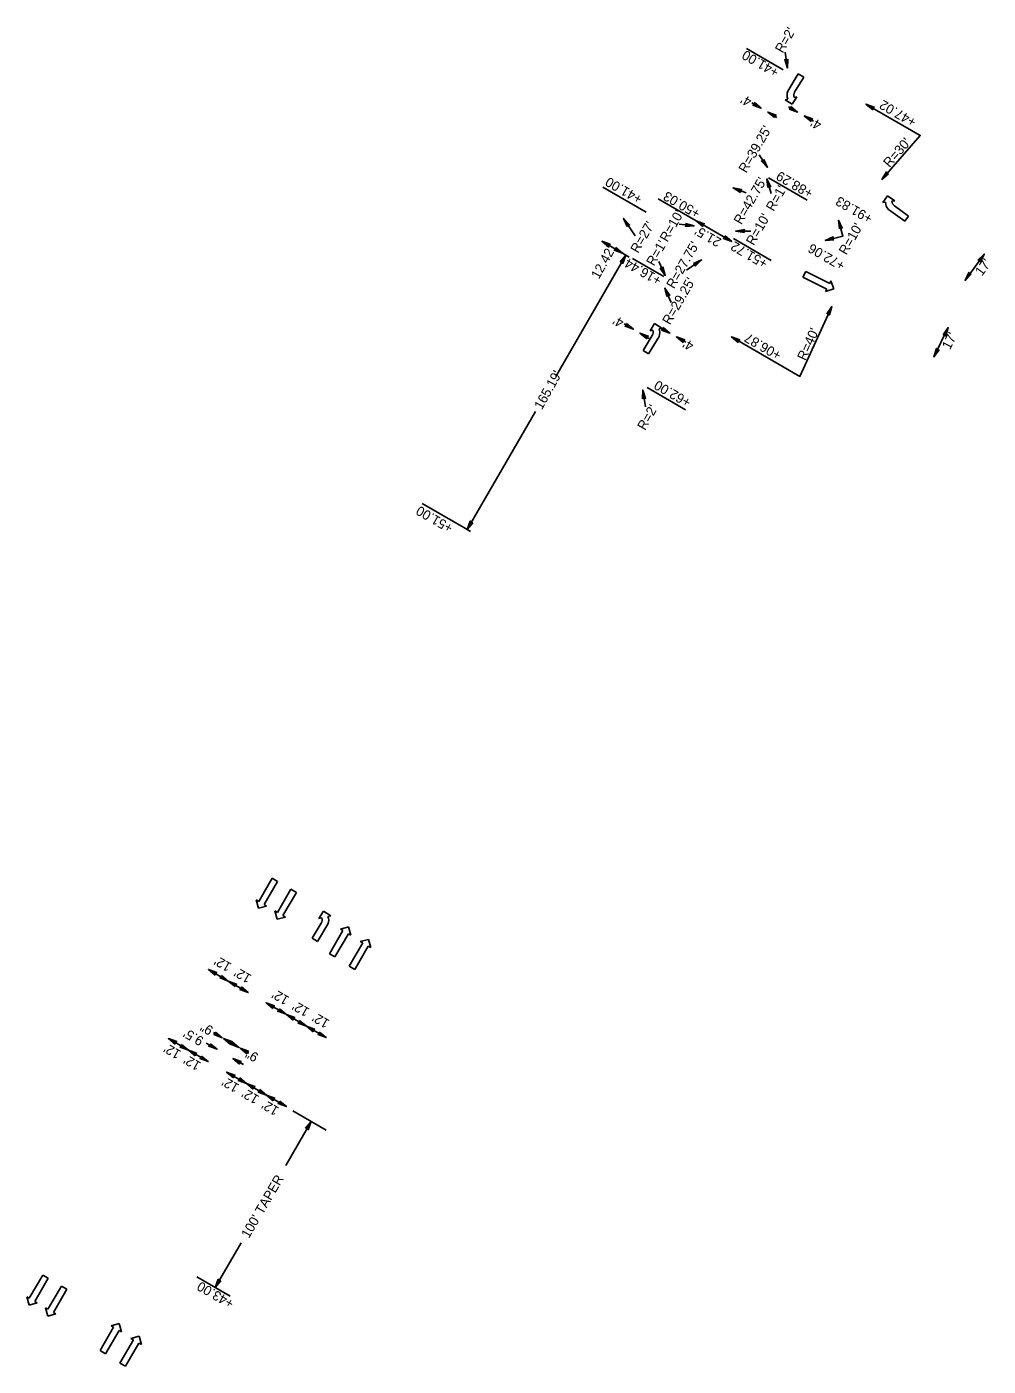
# Model space of a CAD drawing. Extents: x 2320991 to 2332664, y 598057 to 612602.
# Drawn here: x 2329700 to 2330201, y 609336 to 610034 of the extents above; entities that cross this region are included whole.
import ezdxf

# ---------------------------------------------------------------- set-up
doc = ezdxf.new("R2010")
doc.units = 0
for name, color, linetype in [('Prop Dimension', 7, 'Continuous'), ('Prop Dimension Text', 7, 'Continuous'), ('Prop Lane Arrow CELL', 7, 'Continuous'), ('Prop Terminator CELL', 7, 'Continuous')]:
    doc.layers.add(name, color=color, linetype=linetype)

msp = doc.modelspace()

# ---------------------------------------------------------------- linework, layer by layer
at = {"layer": 'Prop Dimension'}
for p, q in [((2330094.28, 610011.7), (2330075.14, 610022.76)), ((2330096.45, 610012.65), (2330095.27, 610020.99)), ((2330077.91, 609994.47), (2330082.72, 609991.69)), ((2330086.18, 609989.69), (2330090.98, 609986.92)), ((2330096.95, 609992.44), (2330101.76, 609989.66)), ((2330105.22, 609987.66), (2330110.02, 609984.88)), ((2330085.97, 609960.8), (2330081.7, 609967.34)), ((2330085.72, 609954.84), (2330087.89, 609947.22)), ((2330086.54, 609955.33), (2330106.75, 609943.66)), ((2330022.81, 609937.49), (2330000.24, 609950.54)), ((2330074.83, 609947.48), (2330068.06, 609950.16)), ((2330048.78, 609932.97), (2330028.97, 609944.42)), ((2330010.96, 609934.18), (2330016.97, 609925.17)), ((2330048.78, 609932.97), (2330067.4, 609922.21)), ((2330047.72, 609930.33), (2330039.95, 609931.17)), ((2330069.52, 609927.59), (2330077.28, 609927.62)), ((2329999.67, 609922.28), (2330010.42, 609916.06)), ((2330068.24, 609923.67), (2330087.95, 609912.28)), ((2329975.62, 609851.84), (2330012.15, 609915.06)), ((2330010.42, 609916.06), (2330013.89, 609914.06)), ((2330031.97, 609903.89), (2330015.68, 609913.31)), ((2330032.69, 609904.48), (2330029.39, 609911.69)), ((2330043.81, 609907.25), (2330051.64, 609912.55)), ((2330189.01, 609901.91), (2330199.02, 609915.65)), ((2330035.8, 609890.29), (2330032.56, 609897.92)), ((2330011.28, 609879.2), (2330016.09, 609876.42)), ((2330030.32, 609877.17), (2330035.13, 609874.39)), ((2330172.77, 609862.03), (2330180.3, 609877.27)), ((2330019.56, 609874.42), (2330024.35, 609871.65)), ((2330038.59, 609872.39), (2330043.39, 609869.62)), ((2330020.98, 609844.73), (2330022.36, 609835.89)), ((2330023.35, 609846), (2330043.34, 609834.44)), ((2329929.49, 609772.03), (2329965.08, 609833.6)), ((2329927.76, 609773.04), (2329906.01, 609785.61)), ((2329927.76, 609773.04), (2329931.23, 609771.03)), ((2329804.93, 609536.53), (2329794.55, 609542.55)), ((2329815.32, 609530.52), (2329804.93, 609536.53)), ((2329835.03, 609519.16), (2329824.65, 609525.18)), ((2329845.63, 609513.03), (2329835.25, 609519.04)), ((2329797.19, 609509.62), (2329801.72, 609506.99)), ((2329802.36, 609506.61), (2329806.89, 609503.99)), ((2329856.02, 609507.02), (2329845.63, 609513.03)), ((2329784.11, 609500.51), (2329773.72, 609506.52)), ((2329794.5, 609494.51), (2329784.11, 609500.51)), ((2329793.46, 609504.19), (2329799.08, 609500.94)), ((2329805.89, 609504.57), (2329810.42, 609501.94)), ((2329811.06, 609501.56), (2329815.59, 609498.94)), ((2329807.31, 609496.18), (2329812.93, 609492.92)), ((2329814.44, 609483.04), (2329804.05, 609489.04)), ((2329824.83, 609477.03), (2329814.44, 609483.04)), ((2329835.22, 609471.03), (2329824.83, 609477.03)), ((2329838.57, 609468.84), (2329855.99, 609458.77)), ((2329834.93, 609440.4), (2329848.17, 609463.29)), ((2329798.13, 609376.72), (2329811.62, 609400.06)), ((2329788.53, 609382.26), (2329805.95, 609372.2))]:
    msp.add_line(p, q, dxfattribs=at)
for points in [[(2330137.36, 609993.8), (2330165.64, 609977.46), (2330145.66, 609954.55)], [(2330116.14, 609922.68), (2330125.33, 609924.99), (2330123.05, 609933.29)], [(2330067.23, 609872.46), (2330102.93, 609851.83), (2330119.58, 609888.31)]]:
    msp.add_lwpolyline(points, dxfattribs=at)
at = {"layer": 'Prop Lane Arrow CELL'}
for p, q in [((2330102.1, 610009.54), (2330096.64, 610000.52)), ((2330104.93, 610007.84), (2330102.1, 610009.54)), ((2330100.19, 610000.01), (2330104.93, 610007.84)), ((2330096.65, 609996.48), (2330095.21, 609996.12)), ((2330095.21, 609996.12), (2330098.95, 609993.8)), ((2330098.95, 609993.8), (2330101.32, 609997.63)), ((2330101.32, 609997.63), (2330099.88, 609997.27)), ((2330146.12, 609942.44), (2330148.68, 609946.03)), ((2330147.59, 609942.67), (2330146.12, 609942.44)), ((2330148.68, 609946.03), (2330152.34, 609943.42)), ((2330152.34, 609943.42), (2330150.87, 609943.19)), ((2330152.22, 609940.78), (2330159.61, 609935.39)), ((2330157.66, 609932.73), (2330149.14, 609938.94)), ((2330159.61, 609935.39), (2330157.66, 609932.73)), ((2330104.46, 609903.64), (2330105.94, 609906.6)), ((2330105.94, 609906.6), (2330118.46, 609900.33)), ((2330116.98, 609897.38), (2330104.46, 609903.64)), ((2330118.46, 609900.33), (2330119.13, 609901.67)), ((2330119.13, 609901.67), (2330120.56, 609897.49)), ((2330120.56, 609897.49), (2330116.31, 609896.04)), ((2330116.31, 609896.04), (2330116.98, 609897.38)), ((2330027.19, 609879.36), (2330024.82, 609875.53)), ((2330030.93, 609877.04), (2330027.19, 609879.36)), ((2330029.48, 609876.68), (2330030.93, 609877.04)), ((2330025.95, 609873.15), (2330021.21, 609865.32)), ((2330024.04, 609863.61), (2330029.5, 609872.64)), ((2330024.82, 609875.53), (2330026.26, 609875.89)), ((2330021.21, 609865.32), (2330024.04, 609863.61)), ((2329820.76, 609578.05), (2329827.81, 609590.15)), ((2329830.66, 609588.49), (2329823.62, 609576.39)), ((2329827.81, 609590.15), (2329830.66, 609588.49)), ((2329830.52, 609572.31), (2329837.56, 609584.41)), ((2329837.56, 609584.41), (2329840.42, 609582.75)), ((2329820.65, 609574.47), (2329819.47, 609578.8)), ((2329819.47, 609578.8), (2329820.76, 609578.05)), ((2329823.62, 609576.39), (2329824.91, 609575.63)), ((2329840.42, 609582.75), (2329833.38, 609570.65)), ((2329824.91, 609575.63), (2329820.65, 609574.47)), ((2329830.41, 609568.73), (2329829.23, 609573.06)), ((2329829.23, 609573.06), (2329830.52, 609572.31)), ((2329834.67, 609569.89), (2329830.41, 609568.73)), ((2329833.38, 609570.65), (2329834.67, 609569.89)), ((2329854.57, 609572.9), (2329852.2, 609569.08)), ((2329852.2, 609569.08), (2329853.64, 609569.43)), ((2329858.31, 609570.58), (2329854.57, 609572.9)), ((2329856.87, 609570.23), (2329858.31, 609570.58)), ((2329853.34, 609566.7), (2329848.6, 609558.87)), ((2329851.42, 609557.16), (2329856.88, 609566.19)), ((2329857.65, 609550.77), (2329864.7, 609562.87)), ((2329863.4, 609563.63), (2329867.66, 609564.79)), ((2329864.7, 609562.87), (2329863.4, 609563.63)), ((2329867.66, 609564.79), (2329868.84, 609560.46)), ((2329848.6, 609558.87), (2329851.42, 609557.16)), ((2329867.55, 609561.21), (2329860.51, 609549.11)), ((2329868.84, 609560.46), (2329867.55, 609561.21)), ((2329868, 609544.26), (2329875.04, 609556.36)), ((2329873.75, 609557.11), (2329878.01, 609558.27)), ((2329875.04, 609556.36), (2329873.75, 609557.11)), ((2329878.01, 609558.27), (2329879.19, 609553.94)), ((2329860.51, 609549.11), (2329857.65, 609550.77)), ((2329877.9, 609554.7), (2329870.85, 609542.6)), ((2329879.19, 609553.94), (2329877.9, 609554.7)), ((2329870.85, 609542.6), (2329868, 609544.26)), ((2329701.17, 609371.11), (2329708.21, 609383.22)), ((2329711.06, 609381.56), (2329704.02, 609369.45)), ((2329708.21, 609383.22), (2329711.06, 609381.56)), ((2329710.92, 609365.37), (2329717.96, 609377.48)), ((2329720.82, 609375.82), (2329713.78, 609363.72)), ((2329717.96, 609377.48), (2329720.82, 609375.82)), ((2329701.05, 609367.54), (2329699.87, 609371.87)), ((2329699.87, 609371.87), (2329701.17, 609371.11)), ((2329705.31, 609368.7), (2329701.05, 609367.54)), ((2329704.02, 609369.45), (2329705.31, 609368.7)), ((2329710.81, 609361.8), (2329709.63, 609366.13)), ((2329709.63, 609366.13), (2329710.92, 609365.37)), ((2329715.07, 609362.96), (2329710.81, 609361.8)), ((2329713.78, 609363.72), (2329715.07, 609362.96)), ((2329738.06, 609343.84), (2329745.1, 609355.94)), ((2329747.95, 609354.28), (2329740.91, 609342.18)), ((2329743.8, 609356.69), (2329748.06, 609357.86)), ((2329745.1, 609355.94), (2329743.8, 609356.69)), ((2329749.25, 609353.53), (2329747.95, 609354.28)), ((2329748.06, 609357.86), (2329749.25, 609353.53)), ((2329748.4, 609337.32), (2329755.44, 609349.42)), ((2329758.3, 609347.76), (2329751.26, 609335.66)), ((2329754.15, 609350.18), (2329758.41, 609351.34)), ((2329755.44, 609349.42), (2329754.15, 609350.18)), ((2329759.59, 609347.01), (2329758.3, 609347.76)), ((2329758.41, 609351.34), (2329759.59, 609347.01)), ((2329740.91, 609342.18), (2329738.06, 609343.84)), ((2329751.26, 609335.66), (2329748.4, 609337.32))]:
    msp.add_line(p, q, dxfattribs=at)
for centre, radius, start, end in [((2330101.48, 609998.52), 5.25, 157.51595, 202.82764), ((2330102.97, 609998.31), 3.27, 148.83987, 198.49805), ((2330152.83, 609942.66), 5.25, 179.90235, 225.21405), ((2330154.13, 609943.42), 3.27, 184.23195, 233.89012), ((2330023.17, 609874.85), 3.27, 328.83987, 18.49805), ((2330024.66, 609874.64), 5.25, 337.51595, 22.82764), ((2329850.55, 609568.39), 3.27, 328.83987, 18.49805), ((2329852.05, 609568.19), 5.25, 337.51595, 22.82764)]:
    msp.add_arc(centre, radius, start, end, dxfattribs=at)
at = {"layer": 'Prop Terminator CELL'}
for points in [[(2330096.59, 610017.21), (2330096.45, 610012.65), (2330095.03, 610017.02), (2330095.9, 610016.56)], [(2330079.21, 609994.61), (2330082.72, 609991.69), (2330078.4, 609993.26), (2330079.3, 609993.67)], [(2330089.69, 609986.77), (2330086.18, 609989.69), (2330090.5, 609988.12), (2330089.6, 609987.71)], [(2330098.25, 609992.58), (2330101.76, 609989.66), (2330097.44, 609991.23), (2330098.34, 609991.63)], [(2330140.87, 609990.88), (2330137.36, 609993.8), (2330141.68, 609992.23), (2330140.78, 609991.83)], [(2330108.73, 609984.73), (2330105.22, 609987.66), (2330109.54, 609986.08), (2330108.64, 609985.68)], [(2330084.16, 609964.99), (2330085.97, 609960.8), (2330082.83, 609964.15), (2330083.81, 609964.11)], [(2330086.21, 609950.3), (2330085.72, 609954.84), (2330087.73, 609950.7), (2330086.81, 609951.04)], [(2330149.2, 609957.44), (2330145.66, 609954.56), (2330148.03, 609958.49), (2330148.26, 609957.53)], [(2330071.96, 609947.78), (2330068.06, 609950.16), (2330072.56, 609949.24), (2330071.73, 609948.7)], [(2330012.81, 609930.01), (2330010.96, 609934.18), (2330014.14, 609930.86), (2330013.15, 609930.89)], [(2330052.29, 609930.05), (2330048.78, 609932.97), (2330053.1, 609931.4), (2330052.2, 609931)], [(2330123.49, 609928.75), (2330123.05, 609933.29), (2330125.02, 609929.14), (2330124.09, 609929.48)], [(2330043.33, 609931.58), (2330047.72, 609930.33), (2330043.14, 609930.02), (2330043.8, 609930.75)], [(2330074.03, 609926.83), (2330069.52, 609927.59), (2330074.05, 609928.41), (2330073.47, 609927.6)], [(2330003.17, 609919.35), (2329999.67, 609922.28), (2330003.98, 609920.7), (2330003.09, 609920.3)], [(2330006.91, 609918.98), (2330010.42, 609916.06), (2330006.1, 609917.63), (2330007, 609918.04)], [(2330063.89, 609925.14), (2330067.4, 609922.21), (2330063.08, 609923.79), (2330063.98, 609924.19)], [(2330120.7, 609923.02), (2330116.14, 609922.68), (2330120.34, 609924.56), (2330119.97, 609923.64)], [(2330009.23, 609911.55), (2330012.15, 609915.06), (2330010.58, 609910.74), (2330010.18, 609911.64)], [(2330047.48, 609910.67), (2330051.64, 609912.55), (2330048.34, 609909.36), (2330048.37, 609910.34)], [(2330047.48, 609910.67), (2330051.64, 609912.55), (2330048.34, 609909.36), (2330048.37, 609910.34)], [(2330195.75, 609912.47), (2330199.02, 609915.65), (2330197, 609911.52), (2330196.7, 609912.46)], [(2330031.52, 609908.89), (2330032.69, 609904.48), (2330030.08, 609908.26), (2330031.04, 609908.07)], [(2330192.29, 609905.09), (2330189.01, 609901.91), (2330191.03, 609906.04), (2330191.34, 609905.1)], [(2330033.61, 609893.47), (2330032.56, 609897.92), (2330035.06, 609894.07), (2330034.1, 609894.28)], [(2330117.01, 609884.54), (2330119.58, 609888.31), (2330118.43, 609883.86), (2330117.94, 609884.72)], [(2330012.58, 609879.35), (2330016.09, 609876.42), (2330011.77, 609877.99), (2330012.67, 609878.4)], [(2330031.62, 609877.31), (2330035.13, 609874.39), (2330030.81, 609875.96), (2330031.71, 609876.37)], [(2330177.62, 609873.58), (2330180.3, 609877.27), (2330179.02, 609872.86), (2330178.55, 609873.73)], [(2330023.06, 609871.5), (2330019.56, 609874.42), (2330023.87, 609872.85), (2330022.98, 609872.44)], [(2330042.1, 609869.46), (2330038.59, 609872.39), (2330042.91, 609870.82), (2330042.01, 609870.41)], [(2330070.74, 609869.54), (2330067.23, 609872.46), (2330071.55, 609870.89), (2330070.65, 609870.49)], [(2330175.46, 609865.72), (2330172.77, 609862.03), (2330174.06, 609866.44), (2330174.52, 609865.57)], [(2330020.91, 609840.16), (2330020.98, 609844.73), (2330022.47, 609840.38), (2330021.59, 609840.83)], [(2329932.42, 609775.54), (2329929.49, 609772.03), (2329931.06, 609776.35), (2329931.47, 609775.45)], [(2329798.05, 609539.62), (2329794.55, 609542.55), (2329798.86, 609540.97), (2329797.96, 609540.57)], [(2329801.43, 609539.46), (2329804.93, 609536.53), (2329800.61, 609538.11), (2329801.51, 609538.51)], [(2329808.44, 609533.61), (2329804.93, 609536.53), (2329809.25, 609534.96), (2329808.35, 609534.56)], [(2329811.81, 609533.45), (2329815.32, 609530.52), (2329811, 609532.1), (2329811.9, 609532.5)], [(2329828.15, 609522.25), (2329824.65, 609525.18), (2329828.96, 609523.6), (2329828.07, 609523.2)], [(2329831.53, 609522.09), (2329835.03, 609519.16), (2329830.72, 609520.74), (2329831.61, 609521.14)], [(2329838.75, 609516.12), (2329835.25, 609519.04), (2329839.56, 609517.47), (2329838.66, 609517.06)], [(2329842.13, 609515.95), (2329845.63, 609513.03), (2329841.31, 609514.6), (2329842.21, 609515.01)], [(2329798.21, 609509.92), (2329801.72, 609506.99), (2329797.4, 609508.57), (2329798.3, 609508.97)], [(2329805.87, 609503.68), (2329802.36, 609506.61), (2329806.68, 609505.03), (2329805.78, 609504.63)], [(2329849.14, 609510.1), (2329845.63, 609513.03), (2329849.95, 609511.45), (2329849.05, 609511.05)], [(2329852.51, 609509.94), (2329856.02, 609507.02), (2329851.7, 609508.59), (2329852.6, 609509)], [(2329777.23, 609503.6), (2329773.72, 609506.52), (2329778.04, 609504.95), (2329777.14, 609504.54)], [(2329780.6, 609503.44), (2329784.11, 609500.51), (2329779.79, 609502.08), (2329780.69, 609502.49)], [(2329787.62, 609497.59), (2329784.11, 609500.51), (2329788.43, 609498.94), (2329787.53, 609498.54)], [(2329795.58, 609503.86), (2329799.08, 609500.94), (2329794.77, 609502.51), (2329795.66, 609502.91)], [(2329806.91, 609504.87), (2329810.42, 609501.94), (2329806.1, 609503.52), (2329807, 609503.92)], [(2329814.57, 609498.63), (2329811.06, 609501.56), (2329815.38, 609499.98), (2329814.48, 609499.58)], [(2329790.99, 609497.43), (2329794.5, 609494.51), (2329790.18, 609496.08), (2329791.08, 609496.48)], [(2329810.81, 609493.25), (2329807.31, 609496.18), (2329811.62, 609494.6), (2329810.72, 609494.2)], [(2329807.56, 609486.12), (2329804.05, 609489.04), (2329808.37, 609487.47), (2329807.47, 609487.07)], [(2329810.93, 609485.96), (2329814.44, 609483.04), (2329810.12, 609484.61), (2329811.02, 609485.01)], [(2329817.95, 609480.12), (2329814.44, 609483.04), (2329818.76, 609481.47), (2329817.86, 609481.06)], [(2329821.32, 609479.96), (2329824.83, 609477.03), (2329820.51, 609478.6), (2329821.41, 609479.01)], [(2329828.34, 609474.11), (2329824.83, 609477.03), (2329829.15, 609475.46), (2329828.25, 609475.06)], [(2329831.71, 609473.95), (2329835.22, 609471.03), (2329830.9, 609472.6), (2329831.8, 609473)], [(2329845.25, 609459.79), (2329848.17, 609463.29), (2329846.6, 609458.98), (2329846.19, 609459.87)], [(2329801.05, 609380.22), (2329798.13, 609376.72), (2329799.7, 609381.03), (2329800.1, 609380.13)]]:
    msp.add_lwpolyline(points, close=True, dxfattribs=at)

# ---------------------------------------------------------------- texts
at = {"layer": 'Prop Dimension'}
for s, p in [('+41.00', (2330092.5, 610011.86)), ('+47.02', (2330164.16, 609985.89)), ('+41.00', (2330021.25, 609945.71)), ('+88.29', (2330110.33, 609948.76)), ('+50.03', (2330051.5, 609938.23)), ('+91.83', (2330141.35, 609935.62)), ('+51.72', (2330086.65, 609912.14)), ('+72.06', (2330126.98, 609911.06)), ('+16.44', (2330031.32, 609903.29)), ('+06.87', (2330093.78, 609864.33)), ('+62.00', (2330046.68, 609839.7)), ('+51.00', (2329922.57, 609774.21)), ('+43.00', (2329808.38, 609369.77))]:
    msp.add_text(s, height=5, rotation=149.97374, dxfattribs=at).set_placement(p)
at = {"layer": 'Prop Dimension Text'}
for s, rotation, p in [("R=2'", 59.97374, (2330093.97, 610020.05)), ("4'", 149.97374, (2330078.3, 609996.48)), ("R=39.25'", 59.97374, (2330074.93, 609957.55)), ("4'", 149.97374, (2330114.75, 609984.38)), ("R=30'", 48.90191, (2330149.65, 609960.39)), ("R=42.75'", 59.97374, (2330072.39, 609930.61)), ("R=1'", 59.97374, (2330089.21, 609937.56)), ("R=27'", 59.97374, (2330018.56, 609915.71)), ("R=10'", 59.97374, (2330033.84, 609921.55)), ("R=10'", 59.97374, (2330078.82, 609919.74)), ("21.5'", 150.21554, (2330062.45, 609923.33)), ("R=10'", 59.97374, (2330127.17, 609914.8)), ("12.42'", 60.87983, (2329998.12, 609902.2)), ("R=1'", 59.97374, (2330026.82, 609909.04)), ("R=27.75'", 59.97374, (2330037.27, 609897.18)), ("17'", 53.90713, (2330197.84, 609903.82)), ("R=29.25'", 59.97374, (2330035.17, 609878.34)), ("4'", 149.97374, (2330011.67, 609881.21)), ("R=40'", 65.47638, (2330105.81, 609859.71)), ("4'", 149.97374, (2330048.12, 609869.11)), ("17'", 63.71106, (2330181.16, 609865.41)), ("165.19'", 60.87983, (2329968.42, 609834.09)), ("R=2'", 59.97374, (2330022.15, 609823.34)), ("12'", 149.93634, (2329807.03, 609545.37)), ("12'", 149.93634, (2329817.42, 609539.36)), ("12'", 149.93634, (2329837.13, 609528)), ("12'", 149.93634, (2329847.73, 609521.87)), ('9"', 149.8653, (2329797.53, 609512.27)), ("12'", 149.93634, (2329858.12, 609515.86)), ("9.5'", 149.93832, (2329792.57, 609506.73)), ("12'", 149.97176, (2329780.69, 609499.81)), ('9"', 149.8653, (2329821.14, 609498.26)), ("12'", 149.97176, (2329791.08, 609493.8)), ("12'", 149.97176, (2329811.02, 609482.33)), ("12'", 149.97176, (2329821.41, 609476.33)), ("12'", 149.97176, (2329831.79, 609470.32)), ("100' TAPER", 59.7789, (2329815.64, 609402))]:
    msp.add_text(s, height=5, rotation=rotation, dxfattribs=at).set_placement(p)

doc.saveas('drawing.dxf')
